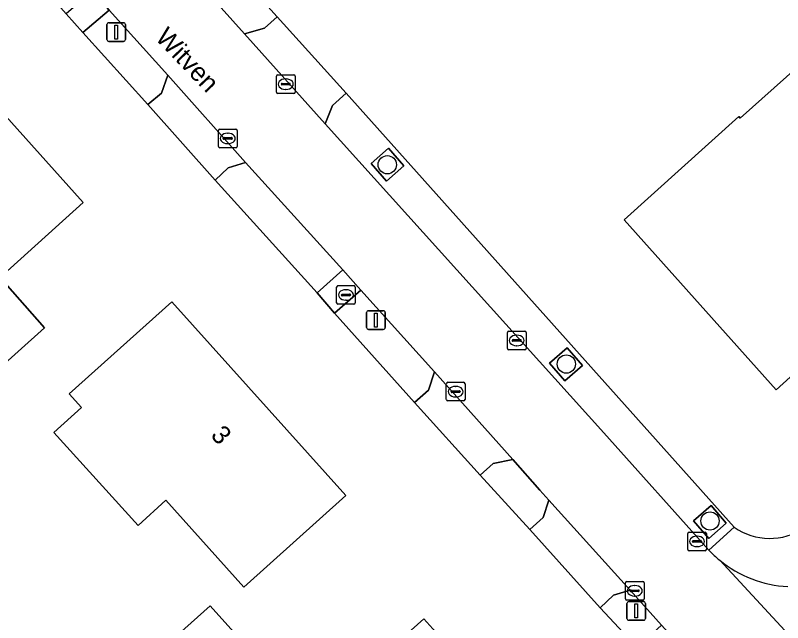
# Model space of a CAD drawing. Extents: x 163266 to 164362, y 381528 to 382286.
# Drawn here: x 163957.2 to 163998.25, y 381754.03 to 381786.54 of the extents above; entities that cross this region are included whole.
import ezdxf

# ---------------------------------------------------------------- set-up
doc = ezdxf.new("R2010")
doc.units = 0
for name, color, linetype in [('IMGEO_Boom', 7, 'Continuous'), ('IMGEO_Brandkraan', 7, 'Continuous'), ('IMGEO_Erf', 7, 'Continuous'), ('IMGEO_Groenvoorziening', 7, 'Continuous'), ('IMGEO_Haag', 7, 'Continuous'), ('IMGEO_Kolk', 7, 'Continuous'), ('IMGEO_Lichtmast', 7, 'Continuous'), ('IMGEO_Openbare_ruimte_label', 7, 'Continuous'), ('IMGEO_Pand', 7, 'Continuous'), ('IMGEO_Pand_nummerreeks', 7, 'Continuous'), ('IMGEO_Rijbaan_lokaal_open', 7, 'Continuous'), ('IMGEO_Voetpad_halfverhard', 7, 'Continuous'), ('IMGEO_Voetpad_open', 7, 'Continuous')]:
    doc.layers.add(name, color=color, linetype=linetype)

msp = doc.modelspace()

# ---------------------------------------------------------------- linework, layer by layer
at = {"layer": 'IMGEO_Boom'}
for centre in [(163977.1, 381778.545), (163986.682, 381767.874), (163994.367, 381759.474)]:
    msp.add_circle(centre, 0.489, dxfattribs=at)
at = {"layer": 'IMGEO_Brandkraan'}
for p, q in [((163974.387, 381771.148), (163974.387, 381772)), ((163974.462, 381772.074), (163975.314, 381772.074)), ((163974.875, 381771.854), (163974.9, 381771.854)), ((163975.388, 381772), (163975.388, 381771.148)), ((163974.646, 381771.568), (163974.646, 381771.58)), ((163975.084, 381771.531), (163974.686, 381771.531)), ((163974.689, 381771.617), (163975.087, 381771.617)), ((163975.13, 381771.58), (163975.13, 381771.568)), ((163975.314, 381771.074), (163974.462, 381771.074)), ((163974.898, 381771.294), (163974.873, 381771.294))]:
    msp.add_line(p, q, dxfattribs=at)
for points in [[(163974.387, 381771.148), (163974.387, 381772)], [(163974.462, 381772.074), (163975.314, 381772.074)], [(163975.388, 381772), (163975.388, 381771.148)], [(163975.314, 381771.074), (163974.462, 381771.074)]]:
    msp.add_lwpolyline(points, dxfattribs=at)
for centre, radius, start, end in [((163974.464, 381771.998), 0.0765, 91.552, 178.448), ((163974.464, 381771.998), 0.0765, 91.552, 178.448), ((163975.312, 381771.998), 0.0765, 1.552, 88.448), ((163975.312, 381771.998), 0.0765, 1.552, 88.448), ((163974.686, 381771.577), 0.0403, 85.8775, 175.7526), ((163974.683, 381771.567), 0.0366, 178.938, 274.7102), ((163975.087, 381771.574), 0.043, 264.8664, 352.4533), ((163975.091, 381771.579), 0.0386, 1.7309, 96.639), ((163974.464, 381771.15), 0.0765, 181.552, 268.448), ((163974.464, 381771.15), 0.0765, 181.552, 268.448), ((163975.312, 381771.15), 0.0765, 271.552, 358.448), ((163975.312, 381771.15), 0.0765, 271.552, 358.448)]:
    msp.add_arc(centre, radius, start, end, dxfattribs=at)
for centre, major_axis, ratio, start_param, end_param in [((163974.874, 381771.574), (-0.387, 0.002), 0.722429, 4.712389, 7.853982), ((163974.899, 381771.574), (-0.39, 0.002), 0.717154, 1.570796, 4.712389)]:
    msp.add_ellipse(centre, major_axis=major_axis, ratio=ratio, start_param=start_param, end_param=end_param, dxfattribs=at)
at = {"layer": 'IMGEO_Erf'}
for points in [[(163995.387, 381745.649), (163992.019, 381749.355), (163989.649, 381751.925), (163990.472, 381752.694), (163988.491, 381754.827), (163984.719, 381759.012), (163982.069, 381761.923), (163978.56, 381765.822), (163974.277, 381770.593), (163973.349, 381771.686), (163967.885, 381777.728), (163964.295, 381781.762), (163960.808, 381785.63), (163959.925, 381786.632), (163952.554, 381794.921), (163948.897, 381798.995), (163947.249, 381800.847), (163946.513, 381801.63), (163938.906, 381810.141)], [(163960.612, 381798.208), (163962.695, 381795.899), (163971.215, 381786.457), (163974.897, 381782.377), (163995.66, 381759.137)]]:
    msp.add_lwpolyline(points, dxfattribs=at)
for points in [[(163943.965, 381780.881), (163951.153, 381787.315), (163960.835, 381776.521), (163956.366, 381772.504), (163958.755, 381769.813), (163952.58, 381764.271), (163948.864, 381768.432), (163950.433, 381769.812), (163952.499, 381771.628)], [(164005.42, 381781.462), (163999.998, 381776.592), (164004.056, 381772.057), (163997.909, 381766.501), (163989.767, 381775.599), (163995.91, 381781.124), (163995.984, 381781.042), (164001.429, 381785.911)], [(163965.246, 381760.582), (163963.764, 381759.239), (163959.258, 381764.212), (163960.741, 381765.555), (163960.075, 381766.289), (163965.567, 381771.211), (163974.889, 381760.835), (163969.419, 381755.929)], [(163961.17, 381749.144), (163967.63, 381754.927), (163970.487, 381751.735), (163964.028, 381745.953)], [(163979.064, 381754.234), (163983.233, 381749.598), (163984.57, 381748.111), (163985.554, 381748.969), (163989.791, 381744.248), (163980.063, 381735.515), (163977.118, 381738.774), (163976.899, 381738.577), (163976.361, 381738.091), (163974.092, 381740.608), (163974.62, 381741.084), (163974.849, 381741.291), (163974.416, 381741.778), (163977.13, 381744.283), (163973.47, 381748.297), (163972.999, 381748.813)]]:
    msp.add_lwpolyline(points, close=True, dxfattribs=at)
msp.add_arc((163997.569, 381761.883), 3.344, 235.1944, 303.3687, dxfattribs=at)
at = {"layer": 'IMGEO_Groenvoorziening'}
for points in [[(163977.993, 381778.485), (163977.173, 381779.429), (163976.229, 381778.608), (163977.05, 381777.665)], [(163987.545, 381767.804), (163986.725, 381768.748), (163985.781, 381767.927), (163986.601, 381766.984)], [(163995.24, 381759.355), (163994.42, 381760.299), (163993.477, 381759.479), (163994.297, 381758.535)]]:
    msp.add_lwpolyline(points, close=True, dxfattribs=at)
at = {"layer": 'IMGEO_Haag'}
for points in [[(163977.993, 381778.485), (163977.173, 381779.429), (163976.229, 381778.608), (163977.05, 381777.665)], [(163987.545, 381767.804), (163986.725, 381768.748), (163985.781, 381767.927), (163986.601, 381766.984)], [(163995.24, 381759.355), (163994.42, 381760.299), (163993.477, 381759.479), (163994.297, 381758.535)]]:
    msp.add_lwpolyline(points, close=True, dxfattribs=at)
at = {"layer": 'IMGEO_Kolk'}
for p, q in [((163971.17, 381782.432), (163971.17, 381783.284)), ((163971.245, 381783.358), (163972.097, 381783.358)), ((163972.171, 381783.284), (163972.171, 381782.432)), ((163971.429, 381782.852), (163971.429, 381782.864)), ((163971.472, 381782.901), (163971.87, 381782.901)), ((163971.658, 381783.138), (163971.683, 381783.138)), ((163971.913, 381782.864), (163971.913, 381782.852)), ((163971.867, 381782.815), (163971.469, 381782.815)), ((163971.681, 381782.578), (163971.656, 381782.578)), ((163972.097, 381782.358), (163971.245, 381782.358)), ((163968.065, 381779.53), (163968.065, 381780.382)), ((163968.14, 381780.456), (163968.992, 381780.456)), ((163969.066, 381780.382), (163969.066, 381779.53)), ((163968.367, 381779.999), (163968.765, 381779.999)), ((163968.553, 381780.236), (163968.578, 381780.236)), ((163968.324, 381779.95), (163968.324, 381779.962)), ((163968.762, 381779.913), (163968.364, 381779.913)), ((163968.576, 381779.676), (163968.551, 381779.676)), ((163968.808, 381779.962), (163968.808, 381779.95)), ((163968.992, 381779.456), (163968.14, 381779.456)), ((163983.525, 381768.712), (163983.525, 381769.564)), ((163983.6, 381769.638), (163984.452, 381769.638)), ((163984.013, 381769.418), (163984.038, 381769.418)), ((163984.526, 381769.564), (163984.526, 381768.712)), ((163983.784, 381769.132), (163983.784, 381769.144)), ((163984.222, 381769.095), (163983.824, 381769.095)), ((163983.827, 381769.181), (163984.225, 381769.181)), ((163984.268, 381769.144), (163984.268, 381769.132)), ((163984.452, 381768.638), (163983.6, 381768.638)), ((163984.036, 381768.858), (163984.011, 381768.858)), ((163980.334, 381766.898), (163981.186, 381766.898)), ((163980.259, 381765.972), (163980.259, 381766.824)), ((163980.561, 381766.441), (163980.959, 381766.441)), ((163980.747, 381766.678), (163980.772, 381766.678)), ((163981.26, 381766.824), (163981.26, 381765.972)), ((163980.518, 381766.392), (163980.518, 381766.404)), ((163980.956, 381766.355), (163980.558, 381766.355)), ((163980.77, 381766.118), (163980.745, 381766.118)), ((163981.002, 381766.404), (163981.002, 381766.392)), ((163981.186, 381765.898), (163980.334, 381765.898)), ((163993.172, 381757.954), (163993.172, 381758.806)), ((163993.247, 381758.88), (163994.099, 381758.88)), ((163993.66, 381758.66), (163993.685, 381758.66)), ((163994.173, 381758.806), (163994.173, 381757.954)), ((163993.431, 381758.374), (163993.431, 381758.386)), ((163993.869, 381758.337), (163993.471, 381758.337)), ((163993.474, 381758.423), (163993.872, 381758.423)), ((163993.915, 381758.386), (163993.915, 381758.374)), ((163994.099, 381757.88), (163993.247, 381757.88)), ((163993.683, 381758.1), (163993.658, 381758.1)), ((163989.84, 381755.309), (163989.84, 381756.161)), ((163989.915, 381756.235), (163990.767, 381756.235)), ((163990.841, 381756.161), (163990.841, 381755.309)), ((163990.142, 381755.778), (163990.54, 381755.778)), ((163990.328, 381756.015), (163990.353, 381756.015)), ((163990.099, 381755.729), (163990.099, 381755.741)), ((163990.537, 381755.692), (163990.139, 381755.692)), ((163990.351, 381755.455), (163990.326, 381755.455)), ((163990.583, 381755.741), (163990.583, 381755.729)), ((163990.767, 381755.235), (163989.915, 381755.235))]:
    msp.add_line(p, q, dxfattribs=at)
for points in [[(163971.17, 381782.432), (163971.17, 381783.284)], [(163971.245, 381783.358), (163972.097, 381783.358)], [(163972.171, 381783.284), (163972.171, 381782.432)], [(163972.097, 381782.358), (163971.245, 381782.358)], [(163968.065, 381779.53), (163968.065, 381780.382)], [(163968.14, 381780.456), (163968.992, 381780.456)], [(163969.066, 381780.382), (163969.066, 381779.53)], [(163968.992, 381779.456), (163968.14, 381779.456)], [(163983.525, 381768.712), (163983.525, 381769.564)], [(163983.6, 381769.638), (163984.452, 381769.638)], [(163984.526, 381769.564), (163984.526, 381768.712)], [(163984.452, 381768.638), (163983.6, 381768.638)], [(163980.334, 381766.898), (163981.186, 381766.898)], [(163980.259, 381765.972), (163980.259, 381766.824)], [(163981.26, 381766.824), (163981.26, 381765.972)], [(163981.186, 381765.898), (163980.334, 381765.898)], [(163993.172, 381757.954), (163993.172, 381758.806)], [(163993.247, 381758.88), (163994.099, 381758.88)], [(163994.173, 381758.806), (163994.173, 381757.954)], [(163994.099, 381757.88), (163993.247, 381757.88)], [(163989.84, 381755.309), (163989.84, 381756.161)], [(163989.915, 381756.235), (163990.767, 381756.235)], [(163990.841, 381756.161), (163990.841, 381755.309)], [(163990.767, 381755.235), (163989.915, 381755.235)]]:
    msp.add_lwpolyline(points, dxfattribs=at)
for centre, radius, start, end in [((163971.247, 381783.282), 0.0765, 91.552, 178.448), ((163971.247, 381783.282), 0.0765, 91.552, 178.448), ((163972.095, 381783.282), 0.0765, 1.552, 88.448), ((163972.095, 381783.282), 0.0765, 1.552, 88.448), ((163971.469, 381782.861), 0.0403, 85.8775, 175.7526), ((163971.466, 381782.851), 0.0366, 178.938, 274.7102), ((163971.87, 381782.858), 0.043, 264.8664, 352.4533), ((163971.874, 381782.863), 0.0386, 1.7309, 96.639), ((163971.247, 381782.434), 0.0765, 181.552, 268.448), ((163971.247, 381782.434), 0.0765, 181.552, 268.448), ((163972.095, 381782.434), 0.0765, 271.552, 358.448), ((163972.095, 381782.434), 0.0765, 271.552, 358.448), ((163968.142, 381780.38), 0.0765, 91.552, 178.448), ((163968.142, 381780.38), 0.0765, 91.552, 178.448), ((163968.99, 381780.38), 0.0765, 1.552, 88.448), ((163968.99, 381780.38), 0.0765, 1.552, 88.448), ((163968.364, 381779.959), 0.0403, 85.8775, 175.7526), ((163968.769, 381779.961), 0.0386, 1.7309, 96.639), ((163968.361, 381779.949), 0.0366, 178.938, 274.7102), ((163968.765, 381779.956), 0.043, 264.8664, 352.4533), ((163968.142, 381779.532), 0.0765, 181.552, 268.448), ((163968.142, 381779.532), 0.0765, 181.552, 268.448), ((163968.99, 381779.532), 0.0765, 271.552, 358.448), ((163968.99, 381779.532), 0.0765, 271.552, 358.448), ((163983.602, 381769.562), 0.0765, 91.552, 178.448), ((163983.602, 381769.562), 0.0765, 91.552, 178.448), ((163984.45, 381769.562), 0.0765, 1.552, 88.448), ((163984.45, 381769.562), 0.0765, 1.552, 88.448), ((163983.824, 381769.141), 0.0403, 85.8775, 175.7526), ((163983.821, 381769.131), 0.0366, 178.938, 274.7102), ((163984.225, 381769.138), 0.043, 264.8664, 352.4533), ((163984.229, 381769.143), 0.0386, 1.7309, 96.639), ((163983.602, 381768.714), 0.0765, 181.552, 268.448), ((163983.602, 381768.714), 0.0765, 181.552, 268.448), ((163984.45, 381768.714), 0.0765, 271.552, 358.448), ((163984.45, 381768.714), 0.0765, 271.552, 358.448), ((163980.336, 381766.822), 0.0765, 91.552, 178.448), ((163980.336, 381766.822), 0.0765, 91.552, 178.448), ((163981.184, 381766.822), 0.0765, 1.552, 88.448), ((163981.184, 381766.822), 0.0765, 1.552, 88.448), ((163980.558, 381766.401), 0.0403, 85.8775, 175.7526), ((163980.963, 381766.403), 0.0386, 1.7309, 96.639), ((163980.555, 381766.391), 0.0366, 178.938, 274.7102), ((163980.959, 381766.398), 0.043, 264.8664, 352.4533), ((163980.336, 381765.974), 0.0765, 181.552, 268.448), ((163980.336, 381765.974), 0.0765, 181.552, 268.448), ((163981.184, 381765.974), 0.0765, 271.552, 358.448), ((163981.184, 381765.974), 0.0765, 271.552, 358.448), ((163993.249, 381758.804), 0.0765, 91.552, 178.448), ((163993.249, 381758.804), 0.0765, 91.552, 178.448), ((163994.097, 381758.804), 0.0765, 1.552, 88.448), ((163994.097, 381758.804), 0.0765, 1.552, 88.448), ((163993.471, 381758.383), 0.0403, 85.8775, 175.7526), ((163993.468, 381758.373), 0.0366, 178.938, 274.7102), ((163993.872, 381758.38), 0.043, 264.8664, 352.4533), ((163993.876, 381758.385), 0.0386, 1.7309, 96.639), ((163993.249, 381757.956), 0.0765, 181.552, 268.448), ((163993.249, 381757.956), 0.0765, 181.552, 268.448), ((163994.097, 381757.956), 0.0765, 271.552, 358.448), ((163994.097, 381757.956), 0.0765, 271.552, 358.448), ((163989.917, 381756.159), 0.0765, 91.552, 178.448), ((163989.917, 381756.159), 0.0765, 91.552, 178.448), ((163990.765, 381756.159), 0.0765, 1.552, 88.448), ((163990.765, 381756.159), 0.0765, 1.552, 88.448), ((163990.139, 381755.738), 0.0403, 85.8775, 175.7526), ((163990.544, 381755.74), 0.0386, 1.7309, 96.639), ((163990.136, 381755.728), 0.0366, 178.938, 274.7102), ((163990.54, 381755.735), 0.043, 264.8664, 352.4533), ((163989.917, 381755.311), 0.0765, 181.552, 268.448), ((163989.917, 381755.311), 0.0765, 181.552, 268.448), ((163990.765, 381755.311), 0.0765, 271.552, 358.448), ((163990.765, 381755.311), 0.0765, 271.552, 358.448)]:
    msp.add_arc(centre, radius, start, end, dxfattribs=at)
for centre, major_axis, ratio, start_param, end_param in [((163971.657, 381782.858), (-0.387, 0.002), 0.722429, 4.712389, 7.853982), ((163971.682, 381782.858), (-0.39, 0.002), 0.717154, 1.570796, 4.712389), ((163968.552, 381779.956), (-0.387, 0.002), 0.722429, 4.712389, 7.853982), ((163968.577, 381779.956), (-0.39, 0.002), 0.717154, 1.570796, 4.712389), ((163984.012, 381769.138), (-0.387, 0.002), 0.722429, 4.712389, 7.853982), ((163984.037, 381769.138), (-0.39, 0.002), 0.717154, 1.570796, 4.712389), ((163980.746, 381766.398), (-0.387, 0.002), 0.722429, 4.712389, 7.853982), ((163980.771, 381766.398), (-0.39, 0.002), 0.717154, 1.570796, 4.712389), ((163993.659, 381758.38), (-0.387, 0.002), 0.722429, 4.712389, 7.853982), ((163993.684, 381758.38), (-0.39, 0.002), 0.717154, 1.570796, 4.712389), ((163990.327, 381755.735), (-0.387, 0.002), 0.722429, 4.712389, 7.853982), ((163990.352, 381755.735), (-0.39, 0.002), 0.717154, 1.570796, 4.712389)]:
    msp.add_ellipse(centre, major_axis=major_axis, ratio=ratio, start_param=start_param, end_param=end_param, dxfattribs=at)
at = {"layer": 'IMGEO_Lichtmast'}
for p, q in [((163962.199, 381786.149), (163962.989, 381786.149)), ((163962.989, 381786.149), (163962.199, 381786.149)), ((163962.099, 381785.249), (163962.099, 381786.049)), ((163962.099, 381786.049), (163962.099, 381785.249)), ((163963.089, 381786.049), (163963.089, 381785.249)), ((163963.089, 381785.249), (163963.089, 381786.049)), ((163962.989, 381785.149), (163962.199, 381785.149)), ((163962.199, 381785.149), (163962.989, 381785.149)), ((163975.996, 381769.829), (163975.996, 381770.629)), ((163975.996, 381770.629), (163975.996, 381769.829)), ((163976.096, 381770.729), (163976.886, 381770.729)), ((163976.886, 381770.729), (163976.096, 381770.729)), ((163976.986, 381770.629), (163976.986, 381769.829)), ((163976.986, 381769.829), (163976.986, 381770.629)), ((163976.886, 381769.729), (163976.096, 381769.729)), ((163976.096, 381769.729), (163976.886, 381769.729)), ((163989.924, 381754.257), (163989.924, 381755.057)), ((163989.924, 381755.057), (163989.924, 381754.257)), ((163990.024, 381755.157), (163990.814, 381755.157)), ((163990.814, 381755.157), (163990.024, 381755.157)), ((163990.914, 381755.057), (163990.914, 381754.257)), ((163990.914, 381754.257), (163990.914, 381755.057)), ((163990.814, 381754.157), (163990.024, 381754.157)), ((163990.024, 381754.157), (163990.814, 381754.157))]:
    msp.add_line(p, q, dxfattribs=at)
for points in [[(163962.519, 381786.024), (163962.669, 381786.024), (163962.669, 381785.274), (163962.519, 381785.274), (163962.519, 381786.024)], [(163976.416, 381770.604), (163976.566, 381770.604), (163976.566, 381769.854), (163976.416, 381769.854), (163976.416, 381770.604)], [(163990.344, 381755.032), (163990.494, 381755.032), (163990.494, 381754.282), (163990.344, 381754.282), (163990.344, 381755.032)]]:
    msp.add_lwpolyline(points, dxfattribs=at)
for centre, start, end in [((163962.199, 381786.049), 90, 180), ((163962.199, 381786.049), 90, 180), ((163962.989, 381786.049), 0, 90), ((163962.989, 381786.049), 360, 90), ((163962.199, 381785.249), 180, 270), ((163962.199, 381785.249), 180, 270), ((163962.989, 381785.249), 270, 0), ((163962.989, 381785.249), 270, 0), ((163976.096, 381770.629), 90, 180), ((163976.096, 381770.629), 90, 180), ((163976.886, 381770.629), 0, 90), ((163976.886, 381770.629), 360, 90), ((163976.096, 381769.829), 180, 270), ((163976.096, 381769.829), 180, 270), ((163976.886, 381769.829), 270, 0), ((163976.886, 381769.829), 270, 0), ((163990.024, 381755.057), 90, 180), ((163990.024, 381755.057), 90, 180), ((163990.814, 381755.057), 0, 90), ((163990.814, 381755.057), 360, 90), ((163990.024, 381754.257), 180, 270), ((163990.024, 381754.257), 180, 270), ((163990.814, 381754.257), 270, 0), ((163990.814, 381754.257), 270, 0)]:
    msp.add_arc(centre, 0.1, start, end, dxfattribs=at)
at = {"layer": 'IMGEO_Pand'}
for points in [[(163943.965, 381780.881), (163952.499, 381771.628), (163950.433, 381769.812), (163948.864, 381768.432), (163952.58, 381764.271), (163958.755, 381769.813), (163956.366, 381772.504), (163960.835, 381776.521), (163951.153, 381787.315)], [(163997.909, 381766.501), (164004.056, 381772.057), (163999.998, 381776.592), (164005.42, 381781.462), (164001.429, 381785.911), (163995.984, 381781.042), (163995.91, 381781.124), (163989.767, 381775.599)], [(163969.419, 381755.929), (163974.889, 381760.835), (163965.567, 381771.211), (163960.075, 381766.289), (163960.741, 381765.555), (163959.258, 381764.212), (163963.764, 381759.239), (163965.246, 381760.582)], [(163964.028, 381745.953), (163970.487, 381751.735), (163967.63, 381754.927), (163961.17, 381749.144)], [(163985.554, 381748.969), (163984.57, 381748.111), (163983.233, 381749.598), (163979.064, 381754.234), (163972.999, 381748.813), (163973.47, 381748.297), (163977.13, 381744.283), (163974.416, 381741.778), (163974.849, 381741.291), (163974.62, 381741.084), (163974.092, 381740.608), (163976.361, 381738.091), (163976.899, 381738.577), (163977.118, 381738.774), (163980.063, 381735.515), (163989.791, 381744.248)]]:
    msp.add_lwpolyline(points, close=True, dxfattribs=at)
at = {"layer": 'IMGEO_Rijbaan_lokaal_open'}
for points in [[(163940.175, 381811.378), (163947.882, 381802.848), (163948.608, 381802.051), (163949.93, 381800.54), (163954.145, 381795.79), (163961.321, 381787.863), (163962.215, 381786.818), (163965.351, 381783.35), (163969.517, 381778.666), (163974.718, 381772.924), (163975.687, 381771.828), (163979.634, 381767.455), (163983.813, 381762.764), (163985.255, 381761.132), (163985.739, 381760.594), (163990.087, 381755.766), (163991.765, 381753.902), (163993.771, 381751.675), (163997.969, 381747.012)], [(163994.308, 381757.913), (163988.685, 381764.198), (163973.777, 381780.744), (163969.469, 381785.552), (163961.328, 381794.641), (163959.042, 381797.193)], [(163994.884, 381757.372), (164005.983, 381745.357)], [(164009.357, 381741.672), (164005.983, 381745.357), (163994.884, 381757.372)]]:
    msp.add_lwpolyline(points, dxfattribs=at)
for centre, radius, start, end in [((163998.916, 381762.242), 6.323, 223.212, 230.3774), ((163998.831, 381762.16), 6.205, 230.5017, 267.2972)]:
    msp.add_arc(centre, radius, start, end, dxfattribs=at)
at = {"layer": 'IMGEO_Voetpad_halfverhard'}
for points in [[(163962.695, 381795.899), (163961.328, 381794.641), (163969.469, 381785.552), (163970.524, 381785.855), (163971.215, 381786.457)], [(163964.295, 381781.762), (163965.014, 381782.384), (163965.351, 381783.35), (163962.215, 381786.818), (163960.808, 381785.63)], [(163988.685, 381764.198), (163994.308, 381757.913), (163995.66, 381759.137), (163974.897, 381782.377), (163974.177, 381781.723), (163973.777, 381780.744)], [(163977.05, 381777.665), (163976.229, 381778.608), (163977.173, 381779.429), (163977.993, 381778.485)], [(163969.517, 381778.666), (163968.586, 381778.373), (163967.885, 381777.728), (163973.349, 381771.686), (163974.718, 381772.924)], [(163979.297, 381766.475), (163979.634, 381767.455), (163975.687, 381771.828), (163974.277, 381770.593), (163978.56, 381765.822)], [(163986.601, 381766.984), (163985.781, 381767.927), (163986.725, 381768.748), (163987.545, 381767.804)], [(163985.255, 381761.132), (163983.813, 381762.764), (163982.771, 381762.546), (163982.069, 381761.923), (163984.719, 381759.012), (163985.435, 381759.667), (163985.739, 381760.594)], [(163994.297, 381758.535), (163993.477, 381759.479), (163994.42, 381760.299), (163995.24, 381759.355)], [(163991.765, 381753.902), (163990.087, 381755.766), (163989.204, 381755.509), (163988.491, 381754.827), (163990.472, 381752.694)]]:
    msp.add_lwpolyline(points, close=True, dxfattribs=at)
at = {"layer": 'IMGEO_Voetpad_open'}
for points in [[(163961.321, 381787.863), (163959.925, 381786.632), (163960.808, 381785.63), (163962.215, 381786.818)], [(163971.215, 381786.457), (163970.524, 381785.855), (163969.469, 381785.552), (163973.777, 381780.744), (163974.177, 381781.723), (163974.897, 381782.377)], [(163969.517, 381778.666), (163965.351, 381783.35), (163965.014, 381782.384), (163964.295, 381781.762), (163967.885, 381777.728), (163968.586, 381778.373)], [(163974.277, 381770.593), (163975.687, 381771.828), (163974.718, 381772.924), (163973.349, 381771.686)], [(163978.56, 381765.822), (163982.069, 381761.923), (163982.771, 381762.546), (163983.813, 381762.764), (163979.634, 381767.455), (163979.297, 381766.475)], [(163985.739, 381760.594), (163985.435, 381759.667), (163984.719, 381759.012), (163988.491, 381754.827), (163989.204, 381755.509), (163990.087, 381755.766)]]:
    msp.add_lwpolyline(points, close=True, dxfattribs=at)
msp.add_lwpolyline([(163995.66, 381759.137), (163994.308, 381757.913)], dxfattribs=at)
for centre, radius, start, end in [((163997.569, 381761.883), 3.344, 235.1944, 303.3687), ((163998.916, 381762.242), 6.323, 223.212, 230.3774), ((163998.831, 381762.16), 6.205, 230.5017, 267.2972)]:
    msp.add_arc(centre, radius, start, end, dxfattribs=at)

# ---------------------------------------------------------------- texts
at = {"layer": 'IMGEO_Openbare_ruimte_label'}
msp.add_text('Witven', height=1, rotation=313.7036, dxfattribs=at).set_placement((163964.638, 381785.294))
at = {"layer": 'IMGEO_Pand_nummerreeks'}
msp.add_text('3', height=1, rotation=311.9365, dxfattribs=at).set_placement((163967.606, 381764.033))

doc.saveas('drawing.dxf')
